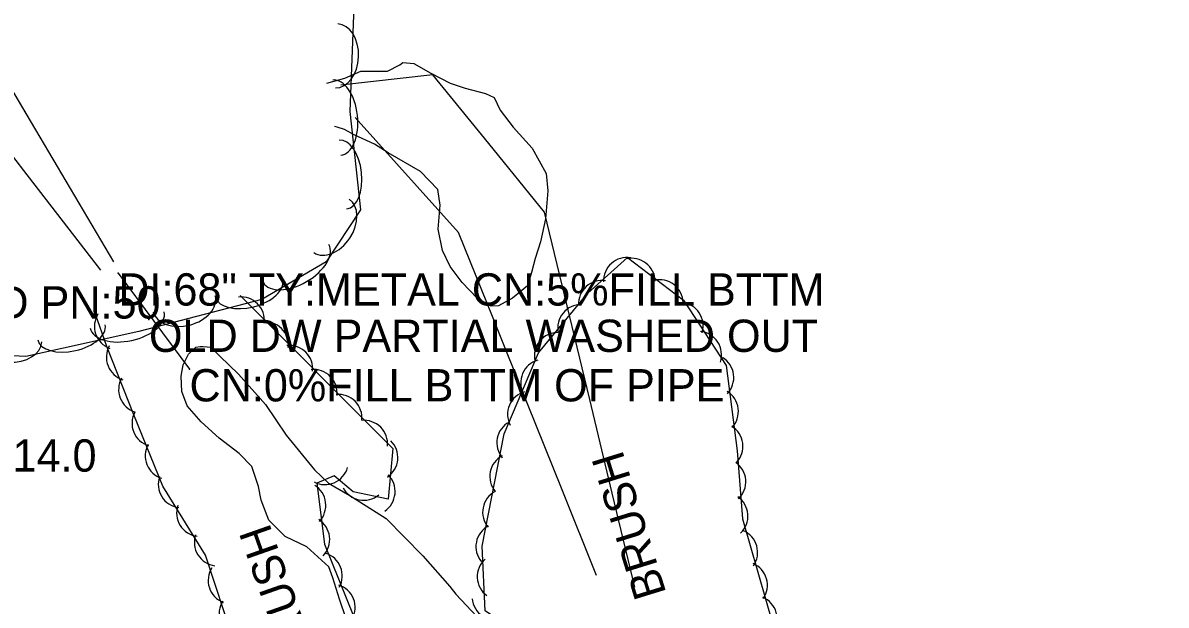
# Model space of a CAD drawing. Extents: x 954793 to 988390, y 1867850 to 1924428.
# Drawn here: x 961253 to 961430.1, y 1907446.8 to 1907537 of the extents above; entities that cross this region are included whole.
import ezdxf

# ---------------------------------------------------------------- set-up
doc = ezdxf.new("R2010")
doc.units = 0
for name, color, linetype in [('S_DITCHLINE', 7, 'Continuous'), ('S_DRG_PT_SYM', 7, 'Continuous'), ('S_GATE_ANNOT', 7, 'Continuous'), ('S_MSC_PT_SYM', 7, 'Continuous'), ('S_PRIMARY_CTL_ANNOT', 7, 'Continuous'), ('S_SIDE_DRAIN', 7, 'Continuous'), ('S_SIDE_DRAIN_ANNOT', 7, 'Continuous'), ('S_STREAM', 7, 'Continuous'), ('S_SURVEY_TEXT_ANNOT', 7, 'Continuous'), ('S_TREE', 7, 'Continuous'), ('S_TREE_ANNOT', 7, 'Continuous')]:
    doc.layers.add(name, color=color, linetype=linetype)

msp = doc.modelspace()

# ---------------------------------------------------------------- linework, layer by layer
at = {"layer": 'S_DITCHLINE'}
for points in [[(961347.79, 1907449.56), (961344.3, 1907464.08), (961340.8, 1907478.6), (961337.31, 1907493.12), (961333.81, 1907507.64), (961325.16, 1907518.27), (961316.5, 1907528.9), (961302.28, 1907527.32)], [(961341.88, 1907451.36), (961336.53, 1907464.64), (961331.18, 1907477.92), (961325.84, 1907491.2), (961320.49, 1907504.48), (961304.46, 1907522.29)]]:
    msp.add_lwpolyline(points, dxfattribs=at)
at = {"layer": 'S_DRG_PT_SYM'}
for points in [[(961267.79, 1907498.17), (961267.79, 1907498.22), (961267.79, 1907498.17), (961267.74, 1907498.17), (961267.79, 1907498.17), (961267.79, 1907498.12), (961267.79, 1907498.17), (961267.84, 1907498.17)], [(961278.82, 1907483.32), (961278.82, 1907483.37), (961278.82, 1907483.32), (961278.77, 1907483.32), (961278.82, 1907483.32), (961278.82, 1907483.27), (961278.82, 1907483.32), (961278.87, 1907483.32)]]:
    msp.add_lwpolyline(points, dxfattribs=at)
for points in [[(961267.79, 1907498.17), (961267.83, 1907498.2), (961267.79, 1907498.17), (961267.76, 1907498.21), (961267.79, 1907498.17), (961267.75, 1907498.14), (961267.79, 1907498.17), (961267.82, 1907498.13)], [(961267.79, 1907498.17), (961267.83, 1907498.2), (961267.79, 1907498.17), (961267.76, 1907498.21), (961267.79, 1907498.17), (961267.75, 1907498.14), (961267.79, 1907498.17), (961267.82, 1907498.13)], [(961278.82, 1907483.32), (961278.86, 1907483.35), (961278.82, 1907483.32), (961278.79, 1907483.36), (961278.82, 1907483.32), (961278.78, 1907483.29), (961278.82, 1907483.32), (961278.85, 1907483.28)], [(961278.82, 1907483.32), (961278.86, 1907483.35), (961278.82, 1907483.32), (961278.79, 1907483.36), (961278.82, 1907483.32), (961278.78, 1907483.29), (961278.82, 1907483.32), (961278.85, 1907483.28)]]:
    msp.add_lwpolyline(points, close=True, dxfattribs=at)
at = {"layer": 'S_MSC_PT_SYM'}
msp.add_lwpolyline([(961272.54, 1907490.99), (961272.54, 1907491.04), (961272.54, 1907490.99), (961272.49, 1907490.99), (961272.54, 1907490.99), (961272.54, 1907490.94), (961272.54, 1907490.99), (961272.59, 1907490.99)], close=True, dxfattribs=at)
msp.add_lwpolyline([(961272.54, 1907490.99), (961272.54, 1907491.04), (961272.54, 1907490.99), (961272.49, 1907490.99), (961272.54, 1907490.99), (961272.54, 1907490.94), (961272.54, 1907490.99), (961272.59, 1907490.99)], close=True, dxfattribs=at)
msp.add_lwpolyline([(961272.54, 1907490.99), (961272.54, 1907491.04), (961272.54, 1907490.99), (961272.49, 1907490.99), (961272.54, 1907490.99), (961272.54, 1907490.94), (961272.54, 1907490.99), (961272.59, 1907490.99)], dxfattribs=at)
at = {"layer": 'S_SIDE_DRAIN'}
msp.add_line((961267.79, 1907498.17), (961278.82, 1907483.32), dxfattribs=at)
msp.add_lwpolyline([(961267.79, 1907498.17), (961278.82, 1907483.32)], dxfattribs=at)
msp.add_lwpolyline([(961267.79, 1907498.17), (961278.82, 1907483.32)], dxfattribs=at)
at = {"layer": 'S_STREAM'}
for points in [[(961265.09, 1907498.65), (961253.16, 1907514.11), (961241.23, 1907529.58), (961229.3, 1907545.05), (961217.37, 1907560.52), (961208.28, 1907580.97), (961196.38, 1907599.97), (961184.48, 1907618.98), (961172.59, 1907637.98), (961160.69, 1907656.98), (961153.56, 1907671.7), (961146.44, 1907686.41), (961139.31, 1907701.13), (961132.19, 1907715.85), (961136.85, 1907731.48), (961141.52, 1907747.11), (961140.01, 1907767.82), (961128.64, 1907775.03), (961117.27, 1907782.24), (961105.89, 1907789.46), (961094.52, 1907796.67)], [(961267.12, 1907499.96), (961257.68, 1907515.85), (961248.25, 1907531.74), (961238.81, 1907547.63), (961229.38, 1907563.51), (961222.7, 1907576.29), (961216.02, 1907589.06), (961204.97, 1907607.11), (961193.93, 1907625.16), (961182.89, 1907643.2), (961171.85, 1907661.25), (961164.03, 1907673.94), (961156.21, 1907686.62), (961148.39, 1907699.3), (961140.57, 1907711.99), (961142.15, 1907727.49), (961143.72, 1907742.99), (961153.28, 1907741.88)], [(961300.09, 1907527.63), (961302.88, 1907528.4), (961305.38, 1907529.47), (961307.48, 1907529.47), (961309.5, 1907529.5), (961311.37, 1907530.49), (961311.88, 1907530.84), (961313.57, 1907530.69), (961316.2, 1907529.17), (961319.2, 1907527.61), (961321.51, 1907526.85), (961324.66, 1907526), (961326.02, 1907525.4), (961326.93, 1907523.42), (961328.94, 1907520.81), (961331.91, 1907517.55), (961334.08, 1907513.61), (961334.3, 1907510.93), (961333.98, 1907506.61), (961333.16, 1907503.06), (961332.37, 1907500.46), (961331.8, 1907498.28), (961331.19, 1907496.24), (961328.86, 1907494.3), (961326.66, 1907493.13), (961325.55, 1907493.07), (961323.39, 1907494.29), (961321.04, 1907496.75), (961319.2, 1907499.2), (961318.03, 1907501.7), (961317.33, 1907505), (961317.66, 1907508.72), (961317.26, 1907511.13), (961314.6, 1907513.93), (961309.61, 1907516.84), (961307.49, 1907518.18), (961304.34, 1907519.63), (961302.82, 1907520.44), (961301.69, 1907520.82), (961301.3, 1907520.89)], [(961303.1, 1907444.63), (961302.06, 1907447.68), (961301.04, 1907450.99), (961300.42, 1907452.71), (961296.97, 1907455.8), (961293.61, 1907457.39), (961291.08, 1907459.93), (961289.94, 1907463), (961289.48, 1907465.16), (961288.49, 1907468.23), (961286.52, 1907470.27), (961283.41, 1907472.64), (961280.64, 1907475.18), (961278.47, 1907477.64), (961277.62, 1907479.87), (961277.52, 1907482.22), (961277.84, 1907484), (961278.67, 1907485.66), (961279.78, 1907486.7), (961280.47, 1907486.84), (961280.92, 1907486.82), (961282.15, 1907486.7)], [(961282.07, 1907486.74), (961286.39, 1907482.54), (961290.58, 1907477.86), (961293.79, 1907473.11), (961298.17, 1907467.73), (961300.36, 1907465.66), (961303.65, 1907463.74), (961309.29, 1907460.2), (961314.94, 1907454.38), (961319.13, 1907449.64), (961320.05, 1907448.47), (961325.73, 1907442.4)]]:
    msp.add_lwpolyline(points, dxfattribs=at)
at = {"layer": 'S_TREE'}
for points in [[(961246.37, 1907648.67), (961264.42, 1907647.15), (961279.33, 1907634.18), (961284.51, 1907620.29), (961286.65, 1907608.57), (961288.11, 1907594.08), (961290.91, 1907578.44), (961298.52, 1907571.98), (961305.71, 1907567.47), (961309.03, 1907554.03), (961304.33, 1907540.89), (961303.66, 1907523.24), (961305.32, 1907507.98), (961299.97, 1907499.93), (961290.03, 1907494.12), (961270.98, 1907489.15), (961253.48, 1907485.27), (961241.18, 1907485.92)], [(961342.22, 1907417.11), (961340.18, 1907428.49), (961331.52, 1907441.21), (961324.6, 1907445.89), (961324.15, 1907455.87), (961327.53, 1907473.29), (961332.88, 1907485.84), (961340.5, 1907495.11), (961346.68, 1907500.64), (961355.31, 1907494.03), (961361.93, 1907483.87), (961363.64, 1907470.68), (961364.45, 1907460.12), (961369.23, 1907443.6), (961376.46, 1907429.23), (961385.12, 1907417.11), (961391, 1907408.17), (961400.75, 1907402.88), (961410.65, 1907401.15), (961417.19, 1907401.91), (961425.65, 1907405.74), (961430.09, 1907409.71)], [(961286.67, 1907494.75), (961310.33, 1907471.03), (961309.6, 1907463.19), (961304.15, 1907464.29), (961301.2, 1907466.81), (961298.54, 1907465.66), (961299.74, 1907456.2), (961304.25, 1907444.93), (961311.92, 1907437.98), (961320.84, 1907430.12), (961335.51, 1907417.96), (961338.78, 1907415.63)], [(961310.79, 1907394.12), (961298.34, 1907391.93), (961288.06, 1907398.31), (961281.79, 1907412.75), (961284.06, 1907427.92), (961285.66, 1907441.17), (961281.31, 1907454.49), (961274.67, 1907465.19), (961270.18, 1907476.23), (961265.99, 1907486.81), (961264.93, 1907489.91), (961264.07, 1907492.39)]]:
    msp.add_lwpolyline(points, dxfattribs=at)
for centre, start, end in [((961346.59, 1907496.99), 81.0315, 182.6284), ((961347.31, 1907496.85), 1.7594, 103.3564), ((961342.7, 1907493.41), 81.0315, 182.6284), ((961351.63, 1907493.53), 1.7594, 103.3564), ((961286.78, 1907490.87), 354.1291, 95.726), ((961339.49, 1907489.69), 89.7812, 191.3781), ((961354.73, 1907490.04), 342.3013, 83.8982), ((961267.73, 1907489.95), 147.9328, 249.5298), ((961290.49, 1907487.04), 354.1291, 95.726), ((961335.88, 1907485.35), 89.7812, 191.3781), ((961357.58, 1907485.53), 342.3013, 83.8982), ((961269.58, 1907485.15), 150.8518, 252.4488), ((961294.27, 1907483.36), 354.1291, 95.726), ((961333.76, 1907481.21), 106.1265, 207.7234), ((961359.48, 1907482.02), 316.6088, 58.2057), ((961298.05, 1907479.63), 354.1291, 95.726), ((961271.48, 1907480.16), 150.8518, 252.4488), ((961301.89, 1907475.77), 354.1291, 95.726), ((961331.72, 1907476.31), 106.1265, 207.7234), ((961360.2, 1907476.77), 316.6088, 58.2057), ((961273.55, 1907474.93), 151.2898, 252.8868), ((961305.85, 1907471.75), 354.1291, 95.726), ((961330.06, 1907471.92), 118.2196, 219.8165), ((961360.9, 1907471.37), 316.6088, 58.2057), ((961307.45, 1907469.63), 303.8641, 45.461), ((961275.59, 1907469.89), 151.2898, 252.8868), ((961328.97, 1907466.7), 118.2196, 219.8165), ((961361.34, 1907465.88), 313.5698, 55.1667), ((961277.61, 1907465.49), 161.0564, 262.6534), ((961299.8, 1907469.07), 242.5313, 344.1282), ((961307.03, 1907464.36), 303.8641, 45.461), ((961296.29, 1907462.22), 316.4847, 58.0816), ((961305.82, 1907466.64), 207.7742, 309.3711), ((961327.86, 1907461.16), 118.2196, 219.8165), ((961361.67, 1907460.56), 313.5698, 55.1667), ((961280.46, 1907461.04), 161.0564, 262.6534), ((961296.9, 1907456.92), 316.4847, 58.0816), ((961326.82, 1907455.82), 118.2196, 219.8165), ((961363.18, 1907454.93), 325.3511, 66.948), ((961283.21, 1907456.47), 161.0564, 262.6534), ((961298.84, 1907451.3), 330.992, 72.5889), ((961285.35, 1907450.58), 147.2912, 248.8881), ((961327.03, 1907451.15), 131.7317, 233.3286), ((961364.69, 1907449.84), 325.3511, 66.948), ((961300.84, 1907446.39), 330.992, 72.5889), ((961287.04, 1907445.41), 147.2912, 248.8881), ((961326.24, 1907448.08), 185.1394, 286.7363), ((961366.2, 1907444.61), 325.3511, 66.948)]:
    msp.add_arc(centre, 3.64, start, end, dxfattribs=at)
for centre, major_axis, ratio in [((961301.61, 1907531.85), (0.19, 4.95), 0.685311), ((961301.63, 1907522.28), (-0.63, 5.83), 0.55008), ((961302.59, 1907513.47), (-0.58, 5.32), 0.540699), ((961300.82, 1907505.5), (2.74, 4.13), 0.685311), ((961295.33, 1907499.67), (5.07, 2.96), 0.55008), ((961288.05, 1907495.79), (5.17, 1.35), 0.540699), ((961278.01, 1907493.44), (4.8, 1.25), 0.685311), ((961269.18, 1907490.92), (5.73, 1.27), 0.55008), ((961260.53, 1907489.01), (5.22, 1.16), 0.540699), ((961250.99, 1907487.79), (4.95, -0.26), 0.685311)]:
    msp.add_ellipse(centre, major_axis=major_axis, ratio=ratio, start_param=3.141593, end_param=6.283185, dxfattribs=at)

# ---------------------------------------------------------------- texts
at = {"layer": 'S_GATE_ANNOT'}
msp.add_text('TY:METAL WD:14.0', height=5, dxfattribs=at).set_placement((961203.86, 1907467.44))
at = {"layer": 'S_PRIMARY_CTL_ANNOT'}
msp.add_text('PD:ARDOT STD. MON. STAMPED PN:50', height=5, dxfattribs=at).set_placement((961148.76, 1907491.16))
at = {"layer": 'S_SIDE_DRAIN_ANNOT'}
for s, p in [('DI:68" TY:METAL CN:5%FILL BTTM ', (961267.79, 1907493.17)), ('CN:0%FILL BTTM OF PIPE', (961278.82, 1907478.32))]:
    msp.add_text(s, height=5, dxfattribs=at).set_placement(p)
at = {"layer": 'S_SURVEY_TEXT_ANNOT'}
msp.add_text('OLD DW PARTIAL WASHED OUT', height=5, dxfattribs=at).set_placement((961272.54, 1907485.99))
at = {"layer": 'S_TREE_ANNOT'}
for rotation, p in [(107.1831, (961352.71, 1907448.61)), (109.3857, (961298.89, 1907437.58))]:
    msp.add_text('BRUSH', height=5, rotation=rotation, dxfattribs=at).set_placement(p)

doc.saveas('drawing.dxf')
